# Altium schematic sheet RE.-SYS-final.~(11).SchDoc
size A3
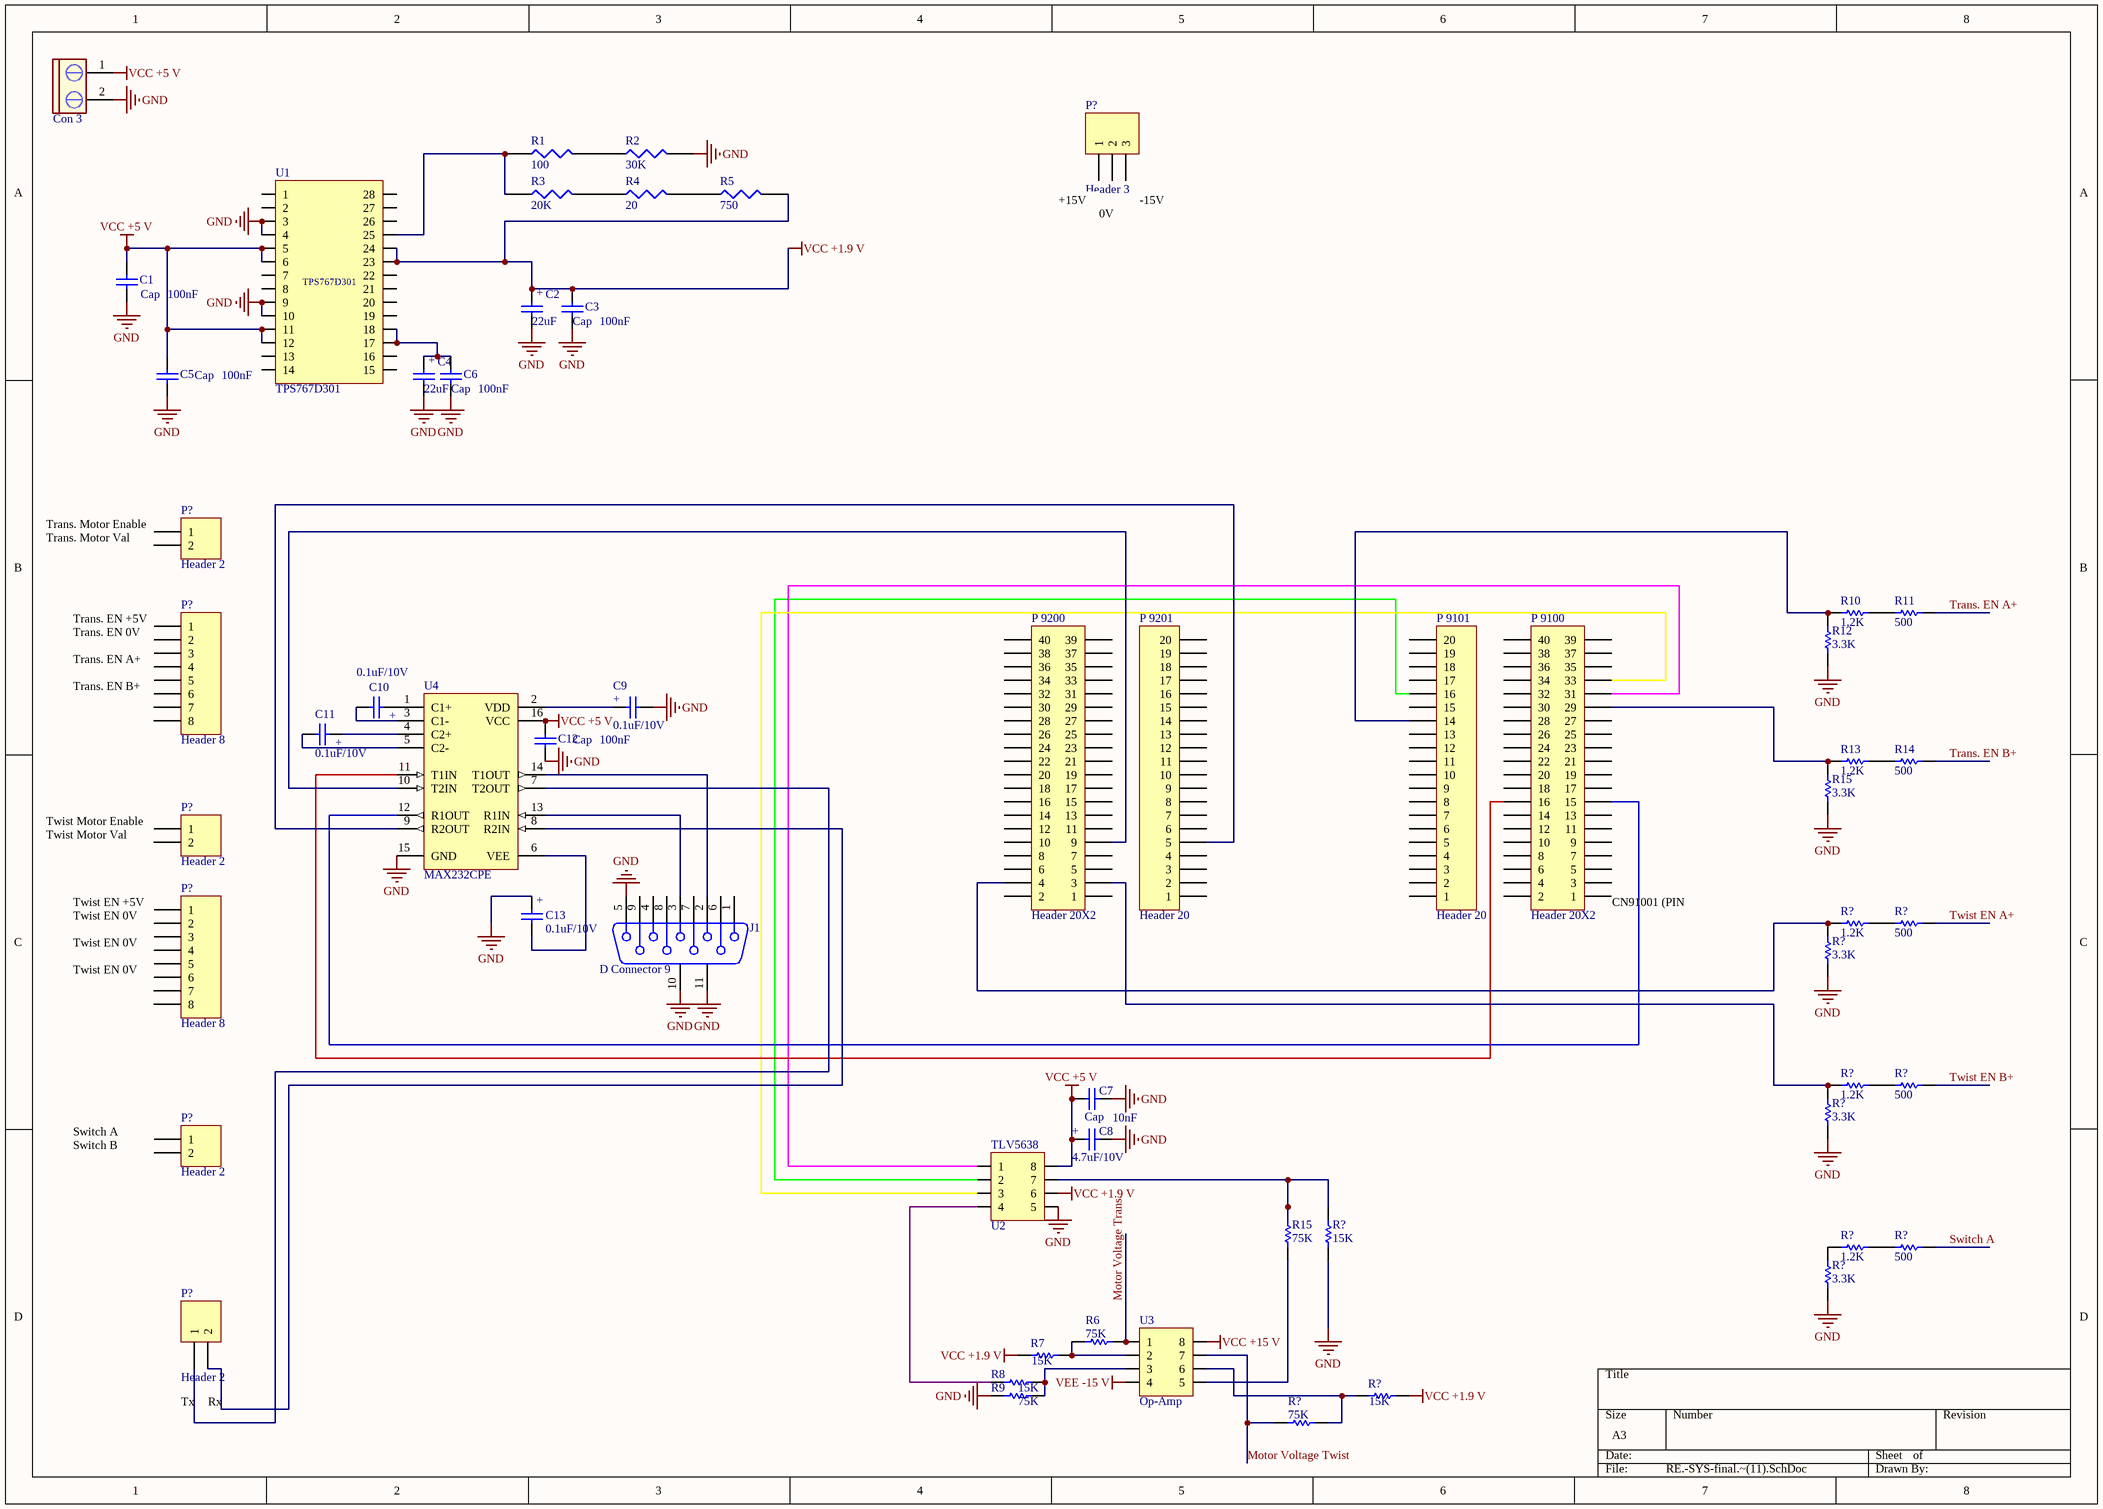
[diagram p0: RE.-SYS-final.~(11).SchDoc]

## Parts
(Parts that share a designator on the sheet are numbered #1, #2 ... from top to bottom, then left to right.)
C1  Cap  value 100nF  [RAD-0.3]
C2  value 22uF  [My_cap3300u]  (hidden comment: Cap)
C3  Cap  value 100nF  [RAD-0.3]
C4  value 22uF  [My_cap3300u]  (hidden comment: Cap)
C5  Cap  value 100nF  [RAD-0.3]
C6  Cap  value 100nF  [RAD-0.3]
C7  Cap  value 10nF  [RAD-0.3]
C8  value 4.7uF/10V  [My_cap3300u]  (hidden comment: Cap)
C9  value 0.1uF/10V  [My_cap3300u]  (hidden comment: Cap)
C10  value 0.1uF/10V  [My_cap3300u]  (hidden comment: Cap)
C11  value 0.1uF/10V  [My_cap3300u]  (hidden comment: Cap)
C12  Cap  value 100nF  [RAD-0.3]
C13  value 0.1uF/10V  [My_cap3300u]  (hidden comment: Cap)
Con_3  CON2 pin blue  [My_CN2]  (value not drawn)
J1  D Connector 9  [DSUB1.385-2H9]
P?#1  Header 3  [HDR1X3]
P?#2  Header 2  [HDR1X2]
P?#3  Header 8  [HDR1X8]
P?#4  Header 2  [HDR1X2]
P?#5  Header 8  [HDR1X8]
P?#6  Header 2  [HDR1X2]
P?#7  Header 2  [HDR1X2]
P_9100  Header 20X2  [HDR2X20]
P_9101  Header 20  [HDR1X20]
P_9200  Header 20X2  [HDR2X20]
P_9201  Header 20  [HDR1X20]
R1  value 100  [My_axial-0.4]  (hidden comment: 1k)
R2  value 30K  [My_axial-0.4]  (hidden comment: 1k)
R3  value 20K  [My_axial-0.4]  (hidden comment: 1k)
R4  value 20  [My_axial-0.4]  (hidden comment: 1k)
R5  value 750  [My_axial-0.4]  (hidden comment: 1k)
R6  value 75K  [AXIAL-0.3]  (hidden comment: Res1)
R7  value 15K  [AXIAL-0.3]  (hidden comment: Res1)
R8  value 15K  [AXIAL-0.3]  (hidden comment: Res1)
R9  value 75K  [AXIAL-0.3]  (hidden comment: Res1)
R10  value 1.2K  [AXIAL-0.3]  (hidden comment: Res1)
R11  value 500  [AXIAL-0.3]  (hidden comment: Res1)
R12  value 3.3K  [AXIAL-0.3]  (hidden comment: Res1)
R13  value 1.2K  [AXIAL-0.3]  (hidden comment: Res1)
R14  value 500  [AXIAL-0.3]  (hidden comment: Res1)
R15#1  value 3.3K  [AXIAL-0.3]  (hidden comment: Res1)
R15#2  value 75K  [AXIAL-0.3]  (hidden comment: Res1)
R?#1  value 1.2K  [AXIAL-0.3]  (hidden comment: Res1)
R?#2  value 500  [AXIAL-0.3]  (hidden comment: Res1)
R?#3  value 3.3K  [AXIAL-0.3]  (hidden comment: Res1)
R?#4  value 1.2K  [AXIAL-0.3]  (hidden comment: Res1)
R?#5  value 500  [AXIAL-0.3]  (hidden comment: Res1)
R?#6  value 3.3K  [AXIAL-0.3]  (hidden comment: Res1)
R?#7  value 15K  [AXIAL-0.3]  (hidden comment: Res1)
R?#8  value 1.2K  [AXIAL-0.3]  (hidden comment: Res1)
R?#9  value 500  [AXIAL-0.3]  (hidden comment: Res1)
R?#10  value 3.3K  [AXIAL-0.3]  (hidden comment: Res1)
R?#11  value 75K  [AXIAL-0.3]  (hidden comment: Res1)
R?#12  value 15K  [AXIAL-0.3]  (hidden comment: Res1)
U1  TPS767D301  [SMD Reg.]
U2  TLV5638  [SMD IC FP]
U3  Op-Amp  [PCBComponent_1]
U4  MAX232CPE  [PE16A]

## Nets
GND: C1.1 C2.- C3.1 C4.- C5.1 C6.1 C7.1 C8.- C9.- C12.1 C13.+ Con_3.2 J1.5 J1.10(MH1) J1.11(MH2) R2.2 R9.1 R12.1 R15#1.1 R?#3.1 R?#6.1 R?#7.2 R?#10.1 U1.3 U1.4 U1.9 U1.10 U2.5 U4.15(GND)
VCC +1.9 V: C2.+ C3.2 R5.2 R7.2 R?#12.1 U1.23 U1.24 U2.6
VCC +5 V: C1.2 C5.2 C7.2 C8.+ C12.2 Con_3.1 U1.5 U1.6 U1.11 U1.12 U2.8 U4.16(VCC)
VCC +15 V: U3.8
VEE -15 V: U3.4
Motor Voltage Trans.: R6.2 U3.1
Motor Voltage Twist: R?#11.1 U3.7
Switch A: R?#9.1
Trans. EN A+: R11.1
Trans. EN B+: R14.1
Twist EN A+: R?#2.1
Twist EN B+: R?#5.1
NetC4_+: C4.+ C6.2 U1.17 U1.18
NetC9_+: C9.+ U4.2(VDD)
NetC10_+: C10.+ U4.1(C1+)
NetC10_-: C10.- U4.3(C1-)
NetC11_+: C11.+ U4.4(C2+)
NetC11_-: C11.- U4.5(C2-)
NetC13_-: C13.- U4.6(VEE)
NetJ1_2: J1.2 U4.14(T1OUT)
NetJ1_3: J1.3 U4.13(R1IN)
NetP?#7_1: P?#7.1 U4.7(T2OUT)
NetP?#7_2: P?#7.2 U4.8(R2IN)
NetP_9100_15: P_9100.15 U4.12(R1OUT)
NetP_9100_16: P_9100.16 U4.11(T1IN)
NetP_9100_29: P_9100.29 R13.2 R15#1.2
NetP_9100_31: P_9100.31 U2.1
NetP_9100_33: P_9100.33 U2.3
NetP_9101_14: P_9101.14 R10.2 R12.2
NetP_9101_16: P_9101.16 U2.2
NetP_9200_3: P_9200.3 R?#4.2 R?#6.2
NetP_9200_4: P_9200.4 R?#1.2 R?#3.2
NetP_9200_9: P_9200.9 U4.10(T2IN)
NetP_9201_5: P_9201.5 U4.9(R2OUT)
NetR1_1: R1.1 R3.1 U1.25
NetR1_2: R1.2 R2.1
NetR3_2: R3.2 R4.1
NetR4_2: R4.2 R5.1
NetR6_1: R6.1 R7.1 U3.2
NetR8_1: R8.1 R9.2 U3.3
NetR8_2: R8.2 U2.4
NetR10_1: R10.1 R11.2
NetR13_1: R13.1 R14.2
NetR15#2_1: R15#2.1 U3.5
NetR15#2_2: R15#2.2 R?#7.1 U2.7
NetR?#1_1: R?#1.1 R?#2.2
NetR?#4_1: R?#4.1 R?#5.2
NetR?#8_1: R?#8.1 R?#9.2
NetR?#8_2: R?#8.2 R?#10.2
NetR?#11_2: R?#11.2 R?#12.2 U3.6

Not connected (* = marked no-connect by the designer): J1 1 4 6 7 8 9; P?#1 1 2 3; P?#2 1 2; P?#3 1 2 3 4 5 6 7 8; P?#4 1 2; P?#5 1 2 3 4 5 6 7 8; P?#6 1 2; P_9100 1 2 3 4 5 6 7 8 9 10 11 12 13 14 17 18 19 20 21 22 23 24 25 26 27 28 30 32 34 35 36 37 38 39 40; P_9101 1 2 3 4 5 6 7 8 9 10 11 12 13 15 17 18 19 20; P_9200 1 2 5 6 7 8 10 11 12 13 14 15 16 17 18 19 20 21 22 23 24 25 26 27 28 29 30 31 32 33 34 35 36 37 38 39 40; P_9201 1 2 3 4 6 7 8 9 10 11 12 13 14 15 16 17 18 19 20; U1 1 2 7 8 13 14 15 16 19 20 21 22 26 27 28

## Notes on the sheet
- (near P?#1) +15V
- (near P?#1) 0V
- (near P?#1) -15V
- (near P?#2) Trans. Motor Enable
- (near P?#2) Trans. Motor Val
- (near P?#3) Trans. EN +5V
- (near P?#3) Trans. EN 0V
- (near P?#3) Trans. EN A+
- (near P?#3) Trans. EN B+
- (near P?#4) Twist Motor Enable
- (near P?#4) Twist Motor Val
- (near P?#5) Twist EN +5V
- (near P?#5) Twist EN 0V
- (near P_9100) CN91001 (PIN 1)
- (near P?#6) Switch A
- (near P?#6) Switch B
- (near P?#7) Tx
- (near P?#7) Rx

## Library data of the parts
C1 C3 C5-C7 C12 = Cap: Capacitor
C2 C4 C8-C11 C13 = Cap Pol: CAP-3300Uf
Con_3 = CON2 pin blue: Connector blue screw
J1 = D Connector 9: Receptacle Assembly, 9 Position, Right Angle; PackageDocument: O; Positions: 9
P?#1 = Header 3: Header, 3-Pin
P?#2 P?#4 P?#6 P?#7 = Header 2: Header, 2-Pin
P?#3 P?#5 = Header 8: Header, 8-Pin
P_9100 P_9200 = Header 20X2: Header, 20-Pin, Dual row
P_9101 P_9201 = Header 20: Header, 20-Pin
R1-R5 = Res: resistor 1/4 wat
R6-R14 R15#1 R15#2 R?#1-R?#12 = Res1: Resistor
U1 = SMD Reg.: Power Reg SMD IC
U2 = SMD IC: DAC
U3 = SMD_Comp.
U4 = MAX232CPE: +5V Powered RS-232 Driver/Receiver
